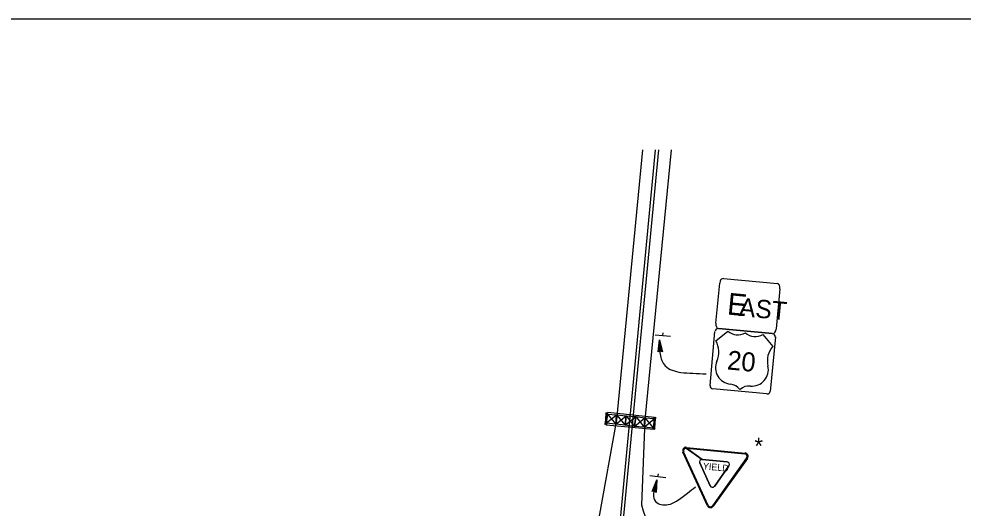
# Model space of a CAD drawing. Extents: x 640994 to 644422, y 298458 to 299646.
# Drawn here: x 641192.3 to 641528.1, y 298862.8 to 299036.6 of the extents above; entities that cross this region are included whole.
import ezdxf

# ---------------------------------------------------------------- set-up
doc = ezdxf.new("R2010")
doc.units = 0
doc.layers.add('1', color=7, linetype='Continuous')
doc.layers.add('2', color=7, linetype='Continuous')

msp = doc.modelspace()

# ---------------------------------------------------------------- linework, layer by layer
at = {"layer": '1'}
msp.add_line((641034.31, 299036.63), (641820.31, 299036.63), dxfattribs=at)
at = {"layer": '2'}
for p, q in [((641418.56, 298990.13), (641373.69, 298519.25)), ((641419.69, 298990.13), (641374.81, 298519.25)), ((641414.06, 298990.13), (641404.81, 298894.25)), ((641424.19, 298990.13), (641414.94, 298894.25)), ((641442.81, 298944.38), (641462.06, 298942.63)), ((641440.19, 298928.5), (641441.56, 298942.75)), ((641462.94, 298940.75), (641461.56, 298926.5)), ((641451.56, 298934.63), (641451.56, 298934.63)), ((641460.31, 298924.88), (641441.06, 298926.63)), ((641441.06, 298926.63), (641460.31, 298924.88)), ((641424.06, 298923.75), (641418.56, 298924.25)), ((641421.31, 298924.13), (641421.44, 298925.13)), ((641438.06, 298906.38), (641439.81, 298925.63)), ((641440.19, 298922.25), (641444.44, 298925.75)), ((641456.81, 298924.5), (641460.44, 298920.25)), ((641461.31, 298923.63), (641459.44, 298904.25)), ((641449.69, 298915), (641449.69, 298915)), ((641458.81, 298911.38), (641458.81, 298911.38)), ((641445.31, 298906.88), (641445.31, 298906.88)), ((641452.44, 298906.13), (641452.44, 298906.13)), ((641458.31, 298903.38), (641439.06, 298905.25)), ((641401.06, 298896.25), (641400.81, 298893)), ((641401.56, 298896.25), (641401.19, 298893)), ((641401.19, 298893), (641404.81, 298896)), ((641401.56, 298896.25), (641404.56, 298892.63)), ((641418.31, 298895), (641401.69, 298896.75)), ((641404.81, 298896), (641407.94, 298892.25)), ((641404.81, 298894.25), (641398.56, 298859.38)), ((641404.56, 298892.63), (641408.19, 298895.63)), ((641404.81, 298894.25), (641404.81, 298894.25)), ((641407.94, 298892.25), (641411.69, 298895.38)), ((641408.19, 298895.63), (641411.19, 298891.88)), ((641409.81, 298893.75), (641409.81, 298893.75)), ((641409.81, 298893.75), (641409.81, 298893.75)), ((641411.19, 298891.88), (641414.94, 298894.88)), ((641411.69, 298895.38), (641414.69, 298891.63)), ((641414.94, 298894.25), (641413.69, 298864)), ((641414.69, 298891.63), (641418.31, 298894.63)), ((641414.94, 298894.88), (641417.94, 298891.25)), ((641414.94, 298894.25), (641414.94, 298894.25)), ((641417.94, 298891.25), (641418.31, 298894.63)), ((641418.44, 298891.25), (641418.69, 298894.63)), ((641401.19, 298892.38), (641417.94, 298890.88)), ((641437.19, 298863.63), (641428.44, 298882.75)), ((641437.44, 298863.75), (641428.69, 298882.88)), ((641437.44, 298863.75), (641428.69, 298882.88)), ((641429.56, 298884.13), (641435.31, 298880.13)), ((641429.69, 298884.38), (641450.56, 298882.38)), ((641429.69, 298884.13), (641450.44, 298882.13)), ((641435.31, 298880.13), (641429.69, 298884.13)), ((641435.31, 298880.13), (641429.69, 298884.13)), ((641429.69, 298884.13), (641450.44, 298882.13)), ((641435.31, 298880.13), (641444.19, 298879.25)), ((641444.19, 298879.25), (641435.31, 298880.13)), ((641451.06, 298880.75), (641438.94, 298863.63)), ((641451.06, 298880.75), (641438.94, 298863.63)), ((641451.44, 298880.5), (641439.19, 298863.5)), ((641438.06, 298870.75), (641434.44, 298878.88)), ((641434.44, 298878.88), (641438.06, 298870.75)), ((641439.44, 298876.13), (641439.44, 298876.13)), ((641444.81, 298877.88), (641439.69, 298870.5)), ((641439.69, 298870.5), (641444.81, 298877.88)), ((641422.31, 298873.63), (641416.69, 298874.25)), ((641419.56, 298874), (641419.69, 298875))]:
    msp.add_line(p, q, dxfattribs=at)
for points in [[(641419.78, 298918.5), (641420.04, 298918.6), (641420.07, 298922.67), (641419.78, 298918.5), (641419.6, 298918.32), (641420.07, 298922.67), (641420.57, 298918.62), (641420.83, 298918.54), (641420.07, 298922.67), (641421.11, 298918.29), (641420.83, 298918.54)], [(641417.69, 298868.91), (641417.97, 298868.93), (641419.12, 298872.83), (641417.69, 298868.91), (641417.47, 298868.78), (641419.12, 298872.83), (641418.48, 298868.8), (641418.72, 298868.65), (641419.12, 298872.83), (641418.91, 298868.33), (641418.72, 298868.65)]]:
    msp.add_lwpolyline(points, dxfattribs=at)
for points in [[(641404.56, 298892.63), (641401.19, 298893), (641401.56, 298896.25), (641404.81, 298896)], [(641407.94, 298892.25), (641404.56, 298892.63), (641404.81, 298896), (641408.19, 298895.63)], [(641411.19, 298891.88), (641407.94, 298892.25), (641408.19, 298895.63), (641411.69, 298895.38)], [(641414.69, 298891.63), (641411.19, 298891.88), (641411.69, 298895.38), (641414.94, 298894.88)], [(641417.94, 298891.25), (641414.69, 298891.63), (641414.94, 298894.88), (641418.31, 298894.63)]]:
    msp.add_lwpolyline(points, close=True, dxfattribs=at)
for centre in [(641401.35, 298896.48), (641401, 298892.72), (641418.5, 298894.85), (641418.14, 298891.09)]:
    msp.add_circle(centre, 0.3, dxfattribs=at)
for centre, radius, start, end in [((641440.96, 298925.54), 1.07, 84.5662, 174.5662), ((641447.91, 298929.6), 5.23, 227.7022, 301.4303), ((641454.15, 298929), 5.23, 227.7022, 301.4303), ((641460.22, 298923.71), 1.07, 354.5662, 84.5662), ((641433.08, 298918.28), 8.13, 336.3952, 29.141), ((641466.58, 298915.09), 8.13, 139.9915, 192.7373), ((641445.85, 298912.66), 5.82, 156.0183, 264.5615), ((641452.98, 298911.98), 5.82, 264.571, 13.1142), ((641439.13, 298906.28), 1.07, 174.5662, 264.5662), ((641444.83, 298901.96), 4.93, 38.2937, 84.5662), ((641451.97, 298901.28), 4.93, 84.5662, 130.8388), ((641458.39, 298904.45), 1.07, 264.5662, 354.5662), ((641429.53, 298883.26), 1.18, 84.5662, 204.5663), ((641429.53, 298883.26), 0.871, 84.5662, 204.5663), ((641429.53, 298883.26), 0.871, 84.5662, 204.5663), ((641450.42, 298881.28), 1.18, 324.5662, 84.5662), ((641435.2, 298879.22), 0.871, 84.5662, 204.5662), ((641435.2, 298879.22), 0.871, 84.5662, 204.5662), ((641444.09, 298878.38), 0.871, 324.5663, 84.5662), ((641444.09, 298878.38), 0.871, 324.5663, 84.5662), ((641450.42, 298881.28), 0.871, 324.5662, 84.5662), ((641450.42, 298881.28), 0.871, 324.5662, 84.5662), ((641438.91, 298871.11), 0.871, 204.5663, 324.5662), ((641438.91, 298871.11), 0.871, 204.5663, 324.5662), ((641442.98, 298870.96), 30.1, 193.3923, 257.789), ((641438.25, 298864.17), 1.18, 204.5663, 324.5662), ((641438.25, 298864.17), 0.871, 204.5663, 324.5662), ((641438.25, 298864.17), 0.871, 204.5663, 324.5662)]:
    msp.add_arc(centre, radius, start, end, dxfattribs=at)
for centre, major_axis, start_param, end_param in [((641442.59, 298942.66), (-0.17, -1.78), 3.141593, 4.712389), ((641461.85, 298940.83), (0.17, 1.78), 4.712389, 6.283185), ((641441.23, 298928.39), (-0.17, -1.78), 4.712389, 6.283185), ((641460.49, 298926.56), (0.17, 1.78), 3.141593, 4.712389)]:
    msp.add_ellipse(centre, major_axis=major_axis, ratio=0.6, start_param=start_param, end_param=end_param, dxfattribs=at)
for points in [[(641420.06, 298922.5), (641420.31, 298917.51), (641422.13, 298913.39), (641427.7, 298911.06), (641431.94, 298910.75), (641436.69, 298910.5)], [(641418.89, 298871.74), (641417.98, 298867.8), (641418.71, 298865.2), (641423.19, 298864.08), (641426.15, 298865.32), (641430.06, 298868.17), (641432.94, 298870.38)]]:
    msp.add_spline(points, degree=3, dxfattribs=at)

# ---------------------------------------------------------------- texts
for s, height, rotation, p in [('E', 7.75, 354.5817, (641443.94, 298931.63)), ('AST', 6.5, 354.5683, (641448.19, 298931.13)), ('20', 6.75, 354.5663, (641443.94, 298912.13)), ('YIELD', 2.383, 354.5663, (641435.44, 298876.63))]:
    msp.add_text(s, height=height, rotation=rotation, dxfattribs=at).set_placement(p)
msp.add_text('*', height=5.85, dxfattribs=at).set_placement((641453.86, 298881.99))

doc.saveas('drawing.dxf')
